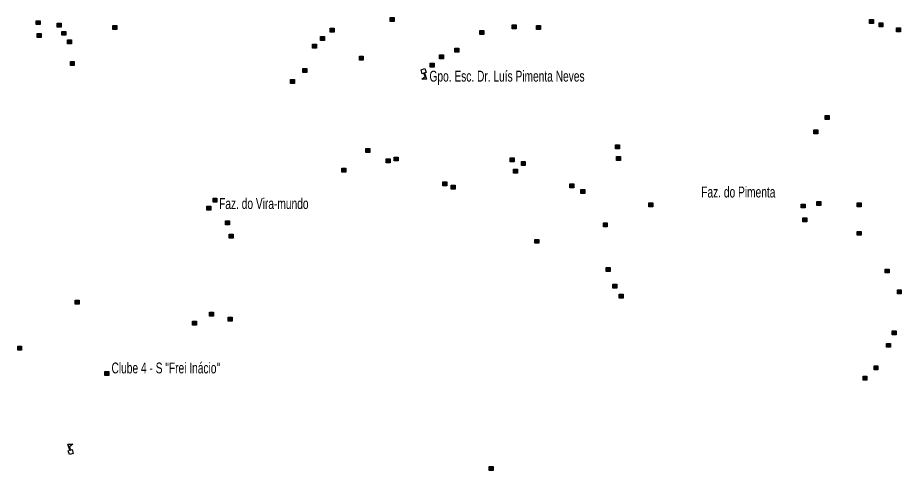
# Model space of a CAD drawing. Extents: x 265.7 to 292.1, y 7676.2 to 7704.2.
# Drawn here: x 279.03 to 285.53, y 7690.21 to 7693.54 of the extents above; entities that cross this region are included whole.
import ezdxf

# ---------------------------------------------------------------- set-up
doc = ezdxf.new("R2010")
doc.units = 0
doc.header["$LTSCALE"] = 0.032
doc.layers.add('2', color=7, linetype='Continuous', lineweight=25)
doc.layers.add('4', color=7, linetype='Continuous', lineweight=25)
doc.layers.add('61', color=7, linetype='Continuous')

msp = doc.modelspace()

# ---------------------------------------------------------------- hatches: boundary and pattern name
at = {"layer": '2'}
for points in [[(279.169, 7693.5167), (279.198, 7693.5167), (279.198, 7693.4877), (279.169, 7693.4877)], [(279.3247, 7693.498), (279.3537, 7693.498), (279.3537, 7693.469), (279.3247, 7693.469)], [(281.7726, 7693.5392), (281.8016, 7693.5392), (281.8016, 7693.5102), (281.7726, 7693.5102)], [(285.297, 7693.5263), (285.326, 7693.5263), (285.326, 7693.4973), (285.297, 7693.4973)], [(285.3672, 7693.5012), (285.3962, 7693.5012), (285.3962, 7693.4722), (285.3672, 7693.4722)], [(279.3579, 7693.4384), (279.3869, 7693.4384), (279.3869, 7693.4094), (279.3579, 7693.4094)], [(279.7339, 7693.4812), (279.7629, 7693.4812), (279.7629, 7693.4522), (279.7339, 7693.4522)], [(281.332, 7693.4619), (281.361, 7693.4619), (281.361, 7693.4329), (281.332, 7693.4329)], [(282.4328, 7693.444), (282.4618, 7693.444), (282.4618, 7693.415), (282.4328, 7693.415)], [(282.6693, 7693.4852), (282.6983, 7693.4852), (282.6983, 7693.4562), (282.6693, 7693.4562)], [(282.8484, 7693.4819), (282.8774, 7693.4819), (282.8774, 7693.4529), (282.8484, 7693.4529)], [(285.4948, 7693.4642), (285.5238, 7693.4642), (285.5238, 7693.4352), (285.4948, 7693.4352)], [(279.1771, 7693.4222), (279.2061, 7693.4222), (279.2061, 7693.3932), (279.1771, 7693.3932)], [(279.3991, 7693.3753), (279.4281, 7693.3753), (279.4281, 7693.3463), (279.3991, 7693.3463)], [(281.2609, 7693.4012), (281.2899, 7693.4012), (281.2899, 7693.3722), (281.2609, 7693.3722)], [(281.2021, 7693.3447), (281.2311, 7693.3447), (281.2311, 7693.3157), (281.2021, 7693.3157)], [(282.2479, 7693.314), (282.2769, 7693.314), (282.2769, 7693.285), (282.2479, 7693.285)], [(281.5458, 7693.2552), (281.5748, 7693.2552), (281.5748, 7693.2262), (281.5458, 7693.2262)], [(282.1349, 7693.2648), (282.1639, 7693.2648), (282.1639, 7693.2358), (282.1349, 7693.2358)], [(279.4208, 7693.2156), (279.4498, 7693.2156), (279.4498, 7693.1866), (279.4208, 7693.1866)], [(282.0671, 7693.2035), (282.0961, 7693.2035), (282.0961, 7693.1745), (282.0671, 7693.1745)], [(281.1301, 7693.1656), (281.1591, 7693.1656), (281.1591, 7693.1366), (281.1301, 7693.1366)], [(281.0406, 7693.0833), (281.0696, 7693.0833), (281.0696, 7693.0543), (281.0406, 7693.0543)], [(284.971, 7692.8186), (285, 7692.8186), (285, 7692.7896), (284.971, 7692.7896)], [(284.8887, 7692.7137), (284.9177, 7692.7137), (284.9177, 7692.6847), (284.8887, 7692.6847)], [(283.4303, 7692.6023), (283.4593, 7692.6023), (283.4593, 7692.5733), (283.4303, 7692.5733)], [(281.5943, 7692.5749), (281.6233, 7692.5749), (281.6233, 7692.5459), (281.5943, 7692.5459)], [(281.7436, 7692.5006), (281.7726, 7692.5006), (281.7726, 7692.4716), (281.7436, 7692.4716)], [(281.8025, 7692.5135), (281.8315, 7692.5135), (281.8315, 7692.4845), (281.8025, 7692.4845)], [(282.6555, 7692.5079), (282.6845, 7692.5079), (282.6845, 7692.4789), (282.6555, 7692.4789)], [(282.737, 7692.4796), (282.766, 7692.4796), (282.766, 7692.4506), (282.737, 7692.4506)], [(283.4367, 7692.5168), (283.4657, 7692.5168), (283.4657, 7692.4878), (283.4367, 7692.4878)], [(281.4167, 7692.4312), (281.4457, 7692.4312), (281.4457, 7692.4022), (281.4167, 7692.4022)], [(282.6797, 7692.4239), (282.7087, 7692.4239), (282.7087, 7692.3949), (282.6797, 7692.3949)], [(282.1592, 7692.3311), (282.1882, 7692.3311), (282.1882, 7692.3021), (282.1592, 7692.3021)], [(282.2213, 7692.3069), (282.2503, 7692.3069), (282.2503, 7692.2779), (282.2213, 7692.2779)], [(283.0929, 7692.3157), (283.1219, 7692.3157), (283.1219, 7692.2867), (283.0929, 7692.2867)], [(283.1745, 7692.2745), (283.2035, 7692.2745), (283.2035, 7692.2455), (283.1745, 7692.2455)], [(280.47, 7692.2093), (280.499, 7692.2093), (280.499, 7692.1803), (280.47, 7692.1803)], [(280.4248, 7692.1511), (280.4538, 7692.1511), (280.4538, 7692.1221), (280.4248, 7692.1221)], [(283.6741, 7692.1761), (283.7031, 7692.1761), (283.7031, 7692.1471), (283.6741, 7692.1471)], [(284.7957, 7692.1672), (284.8247, 7692.1672), (284.8247, 7692.1382), (284.7957, 7692.1382)], [(284.9104, 7692.1858), (284.9394, 7692.1858), (284.9394, 7692.1568), (284.9104, 7692.1568)], [(285.2059, 7692.1761), (285.2349, 7692.1761), (285.2349, 7692.1471), (285.2059, 7692.1471)], [(284.8071, 7692.0664), (284.8361, 7692.0664), (284.8361, 7692.0374), (284.8071, 7692.0374)], [(280.562, 7692.0437), (280.591, 7692.0437), (280.591, 7692.0147), (280.562, 7692.0147)], [(283.3399, 7692.0293), (283.3689, 7692.0293), (283.3689, 7692.0003), (283.3399, 7692.0003)], [(280.5895, 7691.9453), (280.6185, 7691.9453), (280.6185, 7691.9163), (280.5895, 7691.9163)], [(285.2075, 7691.9663), (285.2365, 7691.9663), (285.2365, 7691.9373), (285.2075, 7691.9373)], [(282.8371, 7691.9074), (282.8661, 7691.9074), (282.8661, 7691.8784), (282.8371, 7691.8784)], [(283.3602, 7691.7), (283.3892, 7691.7), (283.3892, 7691.671), (283.3602, 7691.671)], [(285.4116, 7691.6887), (285.4406, 7691.6887), (285.4406, 7691.6597), (285.4116, 7691.6597)], [(283.41, 7691.5781), (283.439, 7691.5781), (283.439, 7691.5491), (283.41, 7691.5491)], [(283.457, 7691.503), (283.486, 7691.503), (283.486, 7691.474), (283.457, 7691.474)], [(285.502, 7691.5353), (285.531, 7691.5353), (285.531, 7691.5063), (285.502, 7691.5063)], [(279.4556, 7691.4603), (279.4846, 7691.4603), (279.4846, 7691.4313), (279.4556, 7691.4313)], [(280.4433, 7691.3715), (280.4723, 7691.3715), (280.4723, 7691.3425), (280.4433, 7691.3425)], [(280.3199, 7691.3045), (280.3489, 7691.3045), (280.3489, 7691.2755), (280.3199, 7691.2755)], [(280.5822, 7691.3351), (280.6112, 7691.3351), (280.6112, 7691.3061), (280.5822, 7691.3061)], [(285.4633, 7691.2335), (285.4923, 7691.2335), (285.4923, 7691.2045), (285.4633, 7691.2045)], [(279.0335, 7691.1205), (279.0625, 7691.1205), (279.0625, 7691.0915), (279.0335, 7691.0915)], [(285.422, 7691.1416), (285.451, 7691.1416), (285.451, 7691.1126), (285.422, 7691.1126)], [(285.3301, 7690.9752), (285.3591, 7690.9752), (285.3591, 7690.9462), (285.3301, 7690.9462)], [(279.6751, 7690.9349), (279.7041, 7690.9349), (279.7041, 7690.9059), (279.6751, 7690.9059)], [(285.2494, 7690.901), (285.2784, 7690.901), (285.2784, 7690.872), (285.2494, 7690.872)], [(282.5014, 7690.2361), (282.5304, 7690.2361), (282.5304, 7690.2071), (282.5014, 7690.2071)]]:
    msp.add_hatch(color=256, dxfattribs=at).paths.add_polyline_path(points)

# ---------------------------------------------------------------- linework, layer by layer
for points in [[(279.169, 7693.5167), (279.198, 7693.5167), (279.198, 7693.4877), (279.169, 7693.4877)], [(279.3247, 7693.498), (279.3537, 7693.498), (279.3537, 7693.469), (279.3247, 7693.469)], [(281.7726, 7693.5392), (281.8016, 7693.5392), (281.8016, 7693.5102), (281.7726, 7693.5102)], [(285.297, 7693.5263), (285.326, 7693.5263), (285.326, 7693.4973), (285.297, 7693.4973)], [(285.3672, 7693.5012), (285.3962, 7693.5012), (285.3962, 7693.4722), (285.3672, 7693.4722)], [(279.3579, 7693.4384), (279.3869, 7693.4384), (279.3869, 7693.4094), (279.3579, 7693.4094)], [(279.7339, 7693.4812), (279.7629, 7693.4812), (279.7629, 7693.4522), (279.7339, 7693.4522)], [(281.332, 7693.4619), (281.361, 7693.4619), (281.361, 7693.4329), (281.332, 7693.4329)], [(282.4328, 7693.444), (282.4618, 7693.444), (282.4618, 7693.415), (282.4328, 7693.415)], [(282.6693, 7693.4852), (282.6983, 7693.4852), (282.6983, 7693.4562), (282.6693, 7693.4562)], [(282.8484, 7693.4819), (282.8774, 7693.4819), (282.8774, 7693.4529), (282.8484, 7693.4529)], [(285.4948, 7693.4642), (285.5238, 7693.4642), (285.5238, 7693.4352), (285.4948, 7693.4352)], [(279.1771, 7693.4222), (279.2061, 7693.4222), (279.2061, 7693.3932), (279.1771, 7693.3932)], [(279.3991, 7693.3753), (279.4281, 7693.3753), (279.4281, 7693.3463), (279.3991, 7693.3463)], [(281.2609, 7693.4012), (281.2899, 7693.4012), (281.2899, 7693.3722), (281.2609, 7693.3722)], [(281.2021, 7693.3447), (281.2311, 7693.3447), (281.2311, 7693.3157), (281.2021, 7693.3157)], [(282.2479, 7693.314), (282.2769, 7693.314), (282.2769, 7693.285), (282.2479, 7693.285)], [(281.5458, 7693.2552), (281.5748, 7693.2552), (281.5748, 7693.2262), (281.5458, 7693.2262)], [(282.1349, 7693.2648), (282.1639, 7693.2648), (282.1639, 7693.2358), (282.1349, 7693.2358)], [(279.4208, 7693.2156), (279.4498, 7693.2156), (279.4498, 7693.1866), (279.4208, 7693.1866)], [(282.0671, 7693.2035), (282.0961, 7693.2035), (282.0961, 7693.1745), (282.0671, 7693.1745)], [(281.1301, 7693.1656), (281.1591, 7693.1656), (281.1591, 7693.1366), (281.1301, 7693.1366)], [(281.0406, 7693.0833), (281.0696, 7693.0833), (281.0696, 7693.0543), (281.0406, 7693.0543)], [(284.971, 7692.8186), (285, 7692.8186), (285, 7692.7896), (284.971, 7692.7896)], [(284.8887, 7692.7137), (284.9177, 7692.7137), (284.9177, 7692.6847), (284.8887, 7692.6847)], [(283.4303, 7692.6023), (283.4593, 7692.6023), (283.4593, 7692.5733), (283.4303, 7692.5733)], [(281.5943, 7692.5749), (281.6233, 7692.5749), (281.6233, 7692.5459), (281.5943, 7692.5459)], [(281.7436, 7692.5006), (281.7726, 7692.5006), (281.7726, 7692.4716), (281.7436, 7692.4716)], [(281.8025, 7692.5135), (281.8315, 7692.5135), (281.8315, 7692.4845), (281.8025, 7692.4845)], [(282.6555, 7692.5079), (282.6845, 7692.5079), (282.6845, 7692.4789), (282.6555, 7692.4789)], [(282.737, 7692.4796), (282.766, 7692.4796), (282.766, 7692.4506), (282.737, 7692.4506)], [(283.4367, 7692.5168), (283.4657, 7692.5168), (283.4657, 7692.4878), (283.4367, 7692.4878)], [(281.4167, 7692.4312), (281.4457, 7692.4312), (281.4457, 7692.4022), (281.4167, 7692.4022)], [(282.6797, 7692.4239), (282.7087, 7692.4239), (282.7087, 7692.3949), (282.6797, 7692.3949)], [(282.1592, 7692.3311), (282.1882, 7692.3311), (282.1882, 7692.3021), (282.1592, 7692.3021)], [(282.2213, 7692.3069), (282.2503, 7692.3069), (282.2503, 7692.2779), (282.2213, 7692.2779)], [(283.0929, 7692.3157), (283.1219, 7692.3157), (283.1219, 7692.2867), (283.0929, 7692.2867)], [(283.1745, 7692.2745), (283.2035, 7692.2745), (283.2035, 7692.2455), (283.1745, 7692.2455)], [(280.47, 7692.2093), (280.499, 7692.2093), (280.499, 7692.1803), (280.47, 7692.1803)], [(280.4248, 7692.1511), (280.4538, 7692.1511), (280.4538, 7692.1221), (280.4248, 7692.1221)], [(283.6741, 7692.1761), (283.7031, 7692.1761), (283.7031, 7692.1471), (283.6741, 7692.1471)], [(284.7957, 7692.1672), (284.8247, 7692.1672), (284.8247, 7692.1382), (284.7957, 7692.1382)], [(284.9104, 7692.1858), (284.9394, 7692.1858), (284.9394, 7692.1568), (284.9104, 7692.1568)], [(285.2059, 7692.1761), (285.2349, 7692.1761), (285.2349, 7692.1471), (285.2059, 7692.1471)], [(284.8071, 7692.0664), (284.8361, 7692.0664), (284.8361, 7692.0374), (284.8071, 7692.0374)], [(280.562, 7692.0437), (280.591, 7692.0437), (280.591, 7692.0147), (280.562, 7692.0147)], [(283.3399, 7692.0293), (283.3689, 7692.0293), (283.3689, 7692.0003), (283.3399, 7692.0003)], [(280.5895, 7691.9453), (280.6185, 7691.9453), (280.6185, 7691.9163), (280.5895, 7691.9163)], [(285.2075, 7691.9663), (285.2365, 7691.9663), (285.2365, 7691.9373), (285.2075, 7691.9373)], [(282.8371, 7691.9074), (282.8661, 7691.9074), (282.8661, 7691.8784), (282.8371, 7691.8784)], [(283.3602, 7691.7), (283.3892, 7691.7), (283.3892, 7691.671), (283.3602, 7691.671)], [(285.4116, 7691.6887), (285.4406, 7691.6887), (285.4406, 7691.6597), (285.4116, 7691.6597)], [(283.41, 7691.5781), (283.439, 7691.5781), (283.439, 7691.5491), (283.41, 7691.5491)], [(283.457, 7691.503), (283.486, 7691.503), (283.486, 7691.474), (283.457, 7691.474)], [(285.502, 7691.5353), (285.531, 7691.5353), (285.531, 7691.5063), (285.502, 7691.5063)], [(279.4556, 7691.4603), (279.4846, 7691.4603), (279.4846, 7691.4313), (279.4556, 7691.4313)], [(280.4433, 7691.3715), (280.4723, 7691.3715), (280.4723, 7691.3425), (280.4433, 7691.3425)], [(280.3199, 7691.3045), (280.3489, 7691.3045), (280.3489, 7691.2755), (280.3199, 7691.2755)], [(280.5822, 7691.3351), (280.6112, 7691.3351), (280.6112, 7691.3061), (280.5822, 7691.3061)], [(285.4633, 7691.2335), (285.4923, 7691.2335), (285.4923, 7691.2045), (285.4633, 7691.2045)], [(279.0335, 7691.1205), (279.0625, 7691.1205), (279.0625, 7691.0915), (279.0335, 7691.0915)], [(285.422, 7691.1416), (285.451, 7691.1416), (285.451, 7691.1126), (285.422, 7691.1126)], [(285.3301, 7690.9752), (285.3591, 7690.9752), (285.3591, 7690.9462), (285.3301, 7690.9462)], [(279.6751, 7690.9349), (279.7041, 7690.9349), (279.7041, 7690.9059), (279.6751, 7690.9059)], [(285.2494, 7690.901), (285.2784, 7690.901), (285.2784, 7690.872), (285.2494, 7690.872)], [(282.5014, 7690.2361), (282.5304, 7690.2361), (282.5304, 7690.2071), (282.5014, 7690.2071)]]:
    msp.add_lwpolyline(points, close=True, dxfattribs=at)
at = {"layer": '4'}
for points in [[(282.0203, 7693.1308), (282.0088, 7693.1268), (281.9993, 7693.1542), (282.0266, 7693.1638), (282.0362, 7693.1363), (282.0249, 7693.1324)], [(282.0249, 7693.1324), (282.0408, 7693.0867), (282.005, 7693.0865), (282.0289, 7693.1062), (282.0203, 7693.1308)], [(279.4174, 7690.3548), (279.4029, 7690.401), (279.4387, 7690.3999), (279.4143, 7690.3811), (279.422, 7690.3562)], [(279.422, 7690.3562), (279.4335, 7690.3598), (279.4422, 7690.3321), (279.4145, 7690.3235), (279.4058, 7690.3512), (279.4174, 7690.3548)]]:
    msp.add_lwpolyline(points, dxfattribs=at)

# ---------------------------------------------------------------- texts
at = {"layer": '61', "width": 0.7}
for s, p in [('Gpo. Esc. Dr. Luís Pimenta Neves', (282.0615, 7693.0686)), ('Faz. do Pimenta', (284.0598, 7692.2155)), ('Faz. do Vira-mundo', (280.5145, 7692.1308)), ('Clube 4 - S "Frei Inácio"', (279.7236, 7690.9208))]:
    msp.add_text(s, height=0.08, dxfattribs=at).set_placement(p)

doc.saveas('drawing.dxf')
